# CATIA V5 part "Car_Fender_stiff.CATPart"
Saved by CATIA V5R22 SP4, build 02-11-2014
Part number: Car_Fender
Material "ｱﾙﾐﾆｳﾑ": density 2710 kg/m3, Young's modulus 7e+10 Pa, Poisson ratio 0.346, thermal expansion 2.36e-05 1/K
Bounding box of the stored display mesh (mm): x -800 to 0, y -40 to 122.298, z 0 to 580
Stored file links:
  \\172.16.16.24\714_東北電子専門学校\2014年度\02_実施プロセス\catia_model_data\CAE_data\Car_modify\Car_Fender_stiff.CATPart
  C:\Program Files\Dassault Systemes\B22\win_b64\startup\materials\red_env_512x512.jpg
  C:\Program Files\Dassault Systemes\B22\win_b64\startup\materials\yellow_env_512x512.jpg

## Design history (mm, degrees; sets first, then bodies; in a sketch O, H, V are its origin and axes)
Set1
  Plane1: type Offset, RefPlane yz-plane, Offset 400, reversed
  Plane2 "平面.2": type Offset, RefPlane Plane1, Offset 400, reversed
  Plane3: type Offset, RefPlane xy-plane, Offset 220
  Plane4: type Offset, RefPlane xy-plane, Offset 370
Body1 (main body)
  Body2
    Sketch1 on yz-plane, origin (0, 0, 0), H (0, 1, 0), V (0, 0, 1)
      point P1 (40.1932, 0)
      point P2 (100, 50)
      line L1 (100, 50) -> (100, 0)
      point P3 (100, 0)
      line L2 (100, 0) -> (0, 0)
      line L3 (0, 0) -> (0, 450)
      line L4 (0, 450) -> (10, 450)
      point P5 (10, 450)
      spline S1 through (10, 450) (100, 50)
      point P6 (10, 450)
      point P7 (100, 50)
      length L3 = 450
      length L2 = 100
      length L1 = 50
      length L4 = 10
      coincidence: P3 H, P6 P5, P7 P2
      vertical: L1 V, L3 V
      horizontal: L2 H, L4 H
    Sketch2 on Plane1, origin (-400, 0, 0), H (0, 1, 0), V (0, 0, 1)
      point P1 (40.1932, 0)
      point P2 (100, 50)
      line L1 (100, 50) -> (100, 0)
      point P3 (100, 0)
      line L2 (100, 0) -> (0, 0)
      line L3 (0, 0) -> (0, 530)
      line L4 (0, 530) -> (10, 530)
      point P5 (10, 530)
      spline S1 through (10, 530) (100, 50)
      point P6 (10, 530)
      point P7 (100, 50)
      length L3 = 530
      length L2 = 100
      length L1 = 50
      length L4 = 10
      coincidence: P3 H, P6 P5, P7 P2
      vertical: L1 V, L3 V
      horizontal: L2 H, L4 H
    Sketch3 on Plane2, origin (-800, 0, 0), H (0, 1, 0), V (0, 0, 1)
      point P1 (40.1932, 0)
      point P2 (100, 50)
      line L1 (100, 50) -> (100, 0)
      point P3 (100, 0)
      line L2 (100, 0) -> (0, 0)
      line L3 (0, 0) -> (0, 580)
      line L4 (0, 580) -> (10, 580)
      point P5 (10, 580)
      spline S1 through (10, 580) (100, 50)
      point P6 (10, 580)
      point P7 (100, 50)
      length L3 = 580
      length L2 = 100
      length L1 = 50
      length L4 = 10
      coincidence: P3 H, P6 P5, P7 P2
      vertical: L1 V, L3 V
      horizontal: L2 H, L4 H
    Loft1: solid, Sections (Sketch1; Sketch2; Sketch3)
    Body3
      Sketch4 on zx-plane, origin (0, 0, 0), H (-1, 0, 0), V (0, 0, 1)
        line L1 (-46.4952, 240) -> (159.0779, 240)
        arc A1 centre (390, 110) radius 265 from (159.0779, 240) to (655, 109.9999) cw
        point P2 (390, 110)
        line L2 (655, 109.9999) -> (655, -30)
        line L3 (-37.8358, 626.6258) -> (859.9489, 626.6258)
        line L4 (859.9489, 626.6258) -> (850, -30)
        line L5 (850, -30) -> (655, -30)
        line L6 (-37.8358, 626.6258) -> (-46.4952, 240)
        radius A1 = 265
        distance P2 H = 110
        distance V P2 = 390
        distance H L1 = 240
        horizontal: L1 H, L3 H, L5 H
        tangency: L2 A1
        vertical: L2 V
      Pad1: profile Sketch4, direction (0, 1, 0), length 340, mirrored extent
    Intersect1: tool Body3
    Sketch5 on Plane2, origin (-800, 0, 0), H (0, 1, 0), V (0, 0, 1)
      line L1 (0, 580) -> (0, 545)
      line L2 (-5, 540) -> (-40, 540)
      point P2 (-40, 540)
      reference projected line E1 (10, 580) -> (0, 580) from edge [face of Loft1 | face of Loft1]
      reference intersected line E2 (0, 0) -> (0, 580) from face of Loft1
      arc A1 centre (-5, 545) radius 5 from (-5, 540) to (0, 545) ccw
      line L3 (-5, 537) -> (-40, 537)
      arc A2 centre (-5, 545) radius 8 from (-5, 537) to (3, 545) ccw
      line L4 (3, 580) -> (3, 545)
      line L5 (-40, 537) -> (-40, 540)
      line L6 (3, 580) -> (0, 580)
      reference projected line E3 (10, 580) -> (0, 580) from edge [face of Loft1 | face of Loft1]
      distance E1 L2 = 40
      radius A1 = 5
      distance L1 P2 = 40
      length L5 = 3
      length L6 = 3
      radius A2 = 8
      vertical: L1 V, L4 V, L5 V
      horizontal: L2 H, L6 H, L3 H
      coincidence: L1 E2, L6 E3
      tangency: A1 L2, A1 L1, L4 A2, A2 L3
    Shell1: ExtOffset 0, Face (face of Loft1; face of Loft1; face of Pad1 from Sketch4.A1; face of Loft1; face of Pad1 from Sketch4.L1; face of Loft1), IntOffset 3
    Rib1: profile Sketch5, centre curve edge [face of Loft1 | face of Loft1]
    Sketch6 on Plane2, origin (-800, 0, 0), H (0, 1, 0), V (0, 0, 1)
      projected line E1 (97, 0) -> (97, 50) from edge [face of Shell1 | face of Rib1]
      projected curve E2 from edge [face of Shell1 | face of Rib1]
      projected line E3 (10, 576.9862) -> (3, 576.9862) from edge [face of Shell1 | face of Rib1]
      point P6 (3, 576.9862)
      projected line E4 (3, 576.9862) -> (3, 545) from edge [face of Rib1 | face of Rib1]
      projected line E5 (3, 576.9862) -> (3, 399.233) from edge [face of Rib1 | face of Rib1]
      point P7 (3, 576.9862)
      line L1 (97, 0) -> (37, 0)
      line L2 (37, 0) -> (17.9077, 155.4943)
      arc A1 centre (2003, 399.233) radius 2000 from (17.9077, 155.4943) to (3, 399.233) cw
      angle L1 L2 = 97
      length L1 = 60
      radius A1 = 2000
      horizontal: L1 H
      coincidence: P6 P7
      tangency: A1 L2, A1 E4
    Pad2: profile Sketch6, direction (1, 0, 0), length 10, opposite side length -7
    Sketch7 on yz-plane, origin (0, 0, 0), H (0, 1, 0), V (0, 0, 1)
      projected curve E1 from edge [face of Loft1 | face of Shell1]
      projected curve E2 from edge [face of Loft1 | face of Shell1]
      line L1 (103.8705, 240) -> (92.1161, 240)
      line L2 (89.1161, 237) -> (89.1161, 160)
      line L3 (89.1161, 160) -> (86.1161, 160)
      line L4 (86.1161, 160) -> (86.1161, 237)
      line L5 (92.1161, 243) -> (100.927, 243)
      offset curve E3 from edge [face of Loft1 | face of Shell1]
      offset curve E4 from edge [face of Loft1 | face of Shell1]
      line L6 (101.1109, 260) -> (104.111, 260)
      reference projected line E5 (0, 240) -> (106.8716, 240) from edge [face of Pad1 from Sketch4.L1 | face of Loft1]
      arc A1 centre (92.1161, 237) radius 3 from (89.1161, 237) to (92.1161, 240) cw
      arc A2 centre (92.1161, 237) radius 6 from (86.1161, 237) to (92.1161, 243) cw
      length L3 = 3
      length L6 = 3
      distance L5 L1 = 3
      distance E5 L3 = 80
      distance L2 E1 = 15
      radius A1 = 3
      radius A2 = 6
      horizontal: L1 H, L3 H, L5 H, L6 H
      vertical: L2 V, L4 V
      tangency: A1 L2, A1 L1, A2 L4, A2 L5
    Rib2: profile Sketch7, centre curve edge [face of Pad1 from Sketch4.L1 | face of Shell1]
    Body4
      Sketch8 on zx-plane, origin (0, 0, 0), H (-1, 0, 0), V (0, 0, 1)
        point P1 (0, 300)
        line L1 (0, 300) -> (127.0171, 520)
        line L2 (127.0171, 520) -> (-100, 520)
        line L3 (-100, 520) -> (-100, 300)
        line L4 (-100, 300) -> (0, 300)
        angle L1 L4 = 120
        distance L4 H = 300
        coincidence: P1 V
        horizontal: L2 H, L4 H
        vertical: L3 V
      Pad3: profile Sketch8, direction (0, 1, 0), length 218, mirrored extent
    Remove1: tool Body4
    Sketch9 on xy-plane, origin (0, 0, 0), H (1, 0, 0), V (0, 1, 0)
      line L1 (-730, -50) -> (-730, -25)
      arc A1 centre (-725, -25) radius 5 from (-730, -25) to (-720, -25) cw
      point P3 (-725, -25)
      line L2 (-720, -25) -> (-720, -50)
      line L3 (-720, -50) -> (-730, -50)
      reference projected line E1 (-800, -40) -> (-800, -5) from edge [face of Rib1 | face of Rib1]
      reference projected line E2 (-5.7993, -40) -> (-800, -40) from edge [face of Rib1 | face of Rib1]
      distance E1 L1 = 70
      length L3 = 10
      distance P3 E2 = 15
      radius A1 = 5
      vertical: L1 V
      tangency: A1 L1, L2 A1
      horizontal: L3 H
    Pocket1: profile Sketch9, direction (0, 0, 1), length 657
    RectPattern1: of Pocket1, direction 1 instances 3, spacing 270, along X axis
    Sketch10 on {plane type Tangent, Support face of Rib2, RefPoint {point type OnSurface, Support face of Rib2, RefPoint {point stored without definition}, Length 0, Direction (0, 0, -1000)}}, origin (-34.1531, 89.7232, 188.2636), H (0.9999, -0.0168, 0), V (0, 0, 1)
      point P1 (-15.8415, 1.7364)
      reference projected line E1 (-124.8302, -28.2636) -> (34.1585, -28.2636) from edge [face of Rib2 | face of Rib2]
      reference projected line E2 (34.1585, -28.2636) -> (34.1585, 48.7364) from edge [face of Rib2 | face of Rib2]
      distance P1 E1 = 30
      distance P1 E2 = 50
    Hole1: placed by Sketch10, at (-49.9925, 89.9835, 190) direction (-0.016, -0.9999, 0), diameter 15, through (limit type 3)
    Fillet1: radius 10, on edge [face of Rib1 | face of Rib1]; edge [face of Rib1 | face of Pad3 from Sketch8.L1]
    Chamfer1: length 70, angle 35, on edge [face of Rib2 | face of Rib2]
    Fillet2: radius 5, on edge [face of Rib2 | face of Rib2]; edge [face of Chamfer1 | face of Rib2]; edge [face of Rib2 | face of Chamfer1]
    Fillet3: radius 10, on edge [face of Pad1 from Sketch4.L2 | face of Pad2]
  Add1: tool Body2
  Stiffener1: ExtendedProfile Sketch12, ThicknessTop 0, ThicknessValue 3
  Stiffener2: ExtendedProfile Sketch13, ThicknessTop 0, ThicknessValue 3
  Sketch11 on end face of Pad2, origin (-790, 0, 0), H (0, 1, 0), V (0, 0, 1)
    projected line E1 (3, 544.0263) -> (3, 399.233) from edge [face of Pad2 from Sketch6.E5 | end face of Pad2]
    projected arc E2 centre (2003, 399.233) radius 2000 from (3, 399.233) to (17.9077, 155.4943) ccw from edge [face of Pad2 from Sketch6.A1 | end face of Pad2]
    projected line E3 (17.9077, 155.4943) -> (37, 0) from edge [face of Pad2 from Sketch6.L2 | end face of Pad2]
  Pad4: profile Sketch11, direction (1, 0, 0), length 50, thin wall 1
Body5
  Sketch12 on Plane3, origin (0, 0, 220), H (1, 0, 0), V (0, 1, 0)
    line L1 (-780, 30) -> (-660, 100)
Body6
  Sketch13 on Plane4, origin (0, 0, 370), H (1, 0, 0), V (0, 1, 0)
    line L1 (-780, 20) -> (-580, 90)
